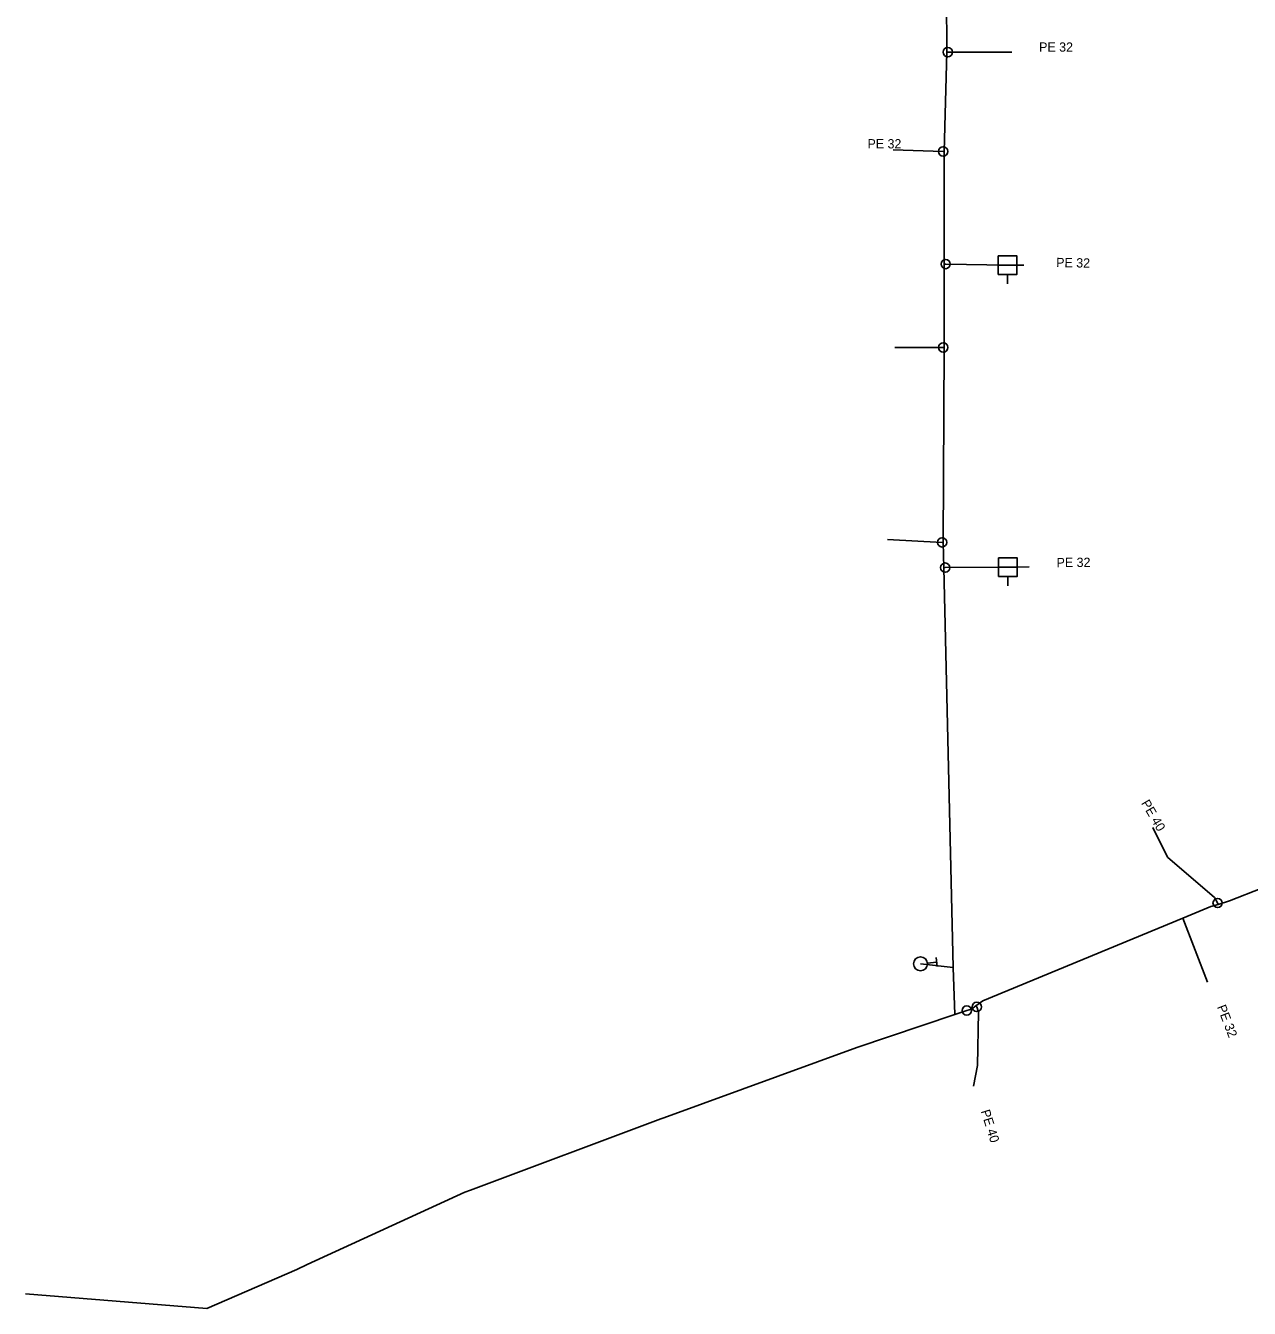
# Model space of a CAD drawing. Extents: x -725126 to -724740, y -1049524 to -1048684.
# Drawn here: x -725125.5 to -724993.9, y -1049075.3 to -1048937.4 of the extents above; entities that cross this region are included whole.
import ezdxf

# ---------------------------------------------------------------- set-up
doc = ezdxf.new("R2010")
doc.units = 0
doc.layers.add('Level 0', color=7, linetype='Continuous')

msp = doc.modelspace()

# ---------------------------------------------------------------- linework, layer by layer
at = {"layer": 'Level 0'}
for p, q in [((-725026.52, -1048928.84), (-725026.44, -1048940.2)), ((-725026.44, -1048940.2), (-725026.74, -1048950.88)), ((-725026.34, -1048940.2), (-725026.44, -1048940.2)), ((-725019.45, -1048940.21), (-725026.34, -1048940.2)), ((-725032.22, -1048950.71), (-725026.84, -1048950.88)), ((-725026.84, -1048950.88), (-725026.74, -1048950.88)), ((-725026.74, -1048950.88), (-725026.73, -1048962.99)), ((-725026.56, -1048962.99), (-725026.73, -1048962.99)), ((-725026.73, -1048962.99), (-725026.72, -1048971.96)), ((-725019.9, -1048963.11), (-725026.56, -1048962.99)), ((-725018.17, -1048963.12), (-725019.9, -1048963.11)), ((-725019.9, -1048965.11), (-725019.9, -1048964.11)), ((-725032.03, -1048971.96), (-725026.82, -1048971.96)), ((-725026.72, -1048971.96), (-725026.84, -1048992.92)), ((-725026.82, -1048971.96), (-725026.72, -1048971.96)), ((-725032.83, -1048992.63), (-725026.94, -1048992.92)), ((-725026.94, -1048992.92), (-725026.84, -1048992.92)), ((-725026.84, -1048992.92), (-725026.77, -1048995.65)), ((-725019.87, -1048995.59), (-725026.61, -1048995.64)), ((-725017.59, -1048995.57), (-725019.87, -1048995.59)), ((-725026.61, -1048995.64), (-725026.77, -1048995.65)), ((-725026.77, -1048995.65), (-725025.75, -1049038.63)), ((-725019.87, -1048997.59), (-725019.87, -1048996.59)), ((-725004.27, -1049023.58), (-725002.7, -1049026.79)), ((-725002.7, -1049026.79), (-724997.65, -1049031.12)), ((-724997.65, -1049031.12), (-724997.31, -1049031.7)), ((-724996.03, -1049031.47), (-724997.25, -1049031.85)), ((-724992.57, -1049030.1), (-724996.03, -1049031.47)), ((-724998.03, -1049032.09), (-725001.04, -1049033.33)), ((-724997.25, -1049031.85), (-724998.03, -1049032.09)), ((-724997.31, -1049031.7), (-724997.25, -1049031.85)), ((-725001.04, -1049033.33), (-725022.57, -1049042.22)), ((-724998.4, -1049040.2), (-725001.04, -1049033.33)), ((-725025.75, -1049038.63), (-725029.27, -1049038.24)), ((-725028.52, -1049038.16), (-725027.53, -1049038.05)), ((-725027.59, -1049037.55), (-725027.48, -1049038.54)), ((-725025.75, -1049038.63), (-725025.58, -1049043.7)), ((-725022.57, -1049042.22), (-725023.3, -1049042.76)), ((-725025.58, -1049043.7), (-725036.1, -1049047.25)), ((-725024.29, -1049043.26), (-725025.58, -1049043.7)), ((-725023.77, -1049043.11), (-725024.29, -1049043.26)), ((-725023.3, -1049042.76), (-725023.77, -1049043.11)), ((-725023.22, -1049042.87), (-725023.3, -1049042.76)), ((-725023.04, -1049043.45), (-725023.22, -1049042.87)), ((-725023.12, -1049049.18), (-725023.04, -1049043.45)), ((-725036.1, -1049047.25), (-725056.88, -1049054.79)), ((-725023.55, -1049051.41), (-725023.12, -1049049.18)), ((-725057.18, -1049054.9), (-725077.68, -1049062.58)), ((-725056.88, -1049054.79), (-725057.18, -1049054.9)), ((-725078.27, -1049062.8), (-725095.22, -1049070.58)), ((-725077.68, -1049062.58), (-725078.27, -1049062.8)), ((-725096.35, -1049071.1), (-725106.01, -1049075.29)), ((-725095.22, -1049070.58), (-725096.35, -1049071.1)), ((-725106.01, -1049075.29), (-725125.51, -1049073.73))]:
    msp.add_line(p, q, dxfattribs=at)
for points in [[(-725020.9, -1048963.11), (-725020.9, -1048962.11), (-725018.9, -1048962.11), (-725018.9, -1048963.11)], [(-725020.87, -1048995.59), (-725020.87, -1048994.59), (-725018.87, -1048994.59), (-725018.87, -1048995.59)]]:
    msp.add_lwpolyline(points, dxfattribs=at)
for points in [[(-725020.9, -1048964.11), (-725018.9, -1048964.11), (-725018.9, -1048963.11), (-725020.9, -1048963.11)], [(-725020.87, -1048996.59), (-725018.87, -1048996.59), (-725018.87, -1048995.59), (-725020.87, -1048995.59)]]:
    msp.add_lwpolyline(points, close=True, dxfattribs=at)
for centre, radius in [((-725026.34, -1048940.2), 0.5), ((-725026.84, -1048950.88), 0.5), ((-725026.56, -1048962.99), 0.5), ((-725026.82, -1048971.96), 0.5), ((-725026.94, -1048992.92), 0.5), ((-725026.61, -1048995.64), 0.5), ((-724997.31, -1049031.7), 0.5), ((-725029.27, -1049038.24), 0.75), ((-725023.22, -1049042.87), 0.5), ((-725024.29, -1049043.26), 0.5)]:
    msp.add_circle(centre, radius, dxfattribs=at)

# ---------------------------------------------------------------- texts
for p in [(-725016.51, -1048940.16), (-725034.97, -1048950.56)]:
    msp.add_text('PE 32', height=1, dxfattribs=at).set_placement(p)
for s, rotation, p in [('PE 32', 358.968, (-725014.68, -1048963.32)), ('PE 32', 0.425, (-725014.63, -1048995.59)), ('PE 40', 300.379, (-725005.57, -1049020.96)), ('PE 32', 291.021, (-724997.4, -1049042.87)), ('PE 40', 287.241, (-725022.79, -1049054.09))]:
    msp.add_text(s, height=1, rotation=rotation, dxfattribs=at).set_placement(p)

doc.saveas('drawing.dxf')
